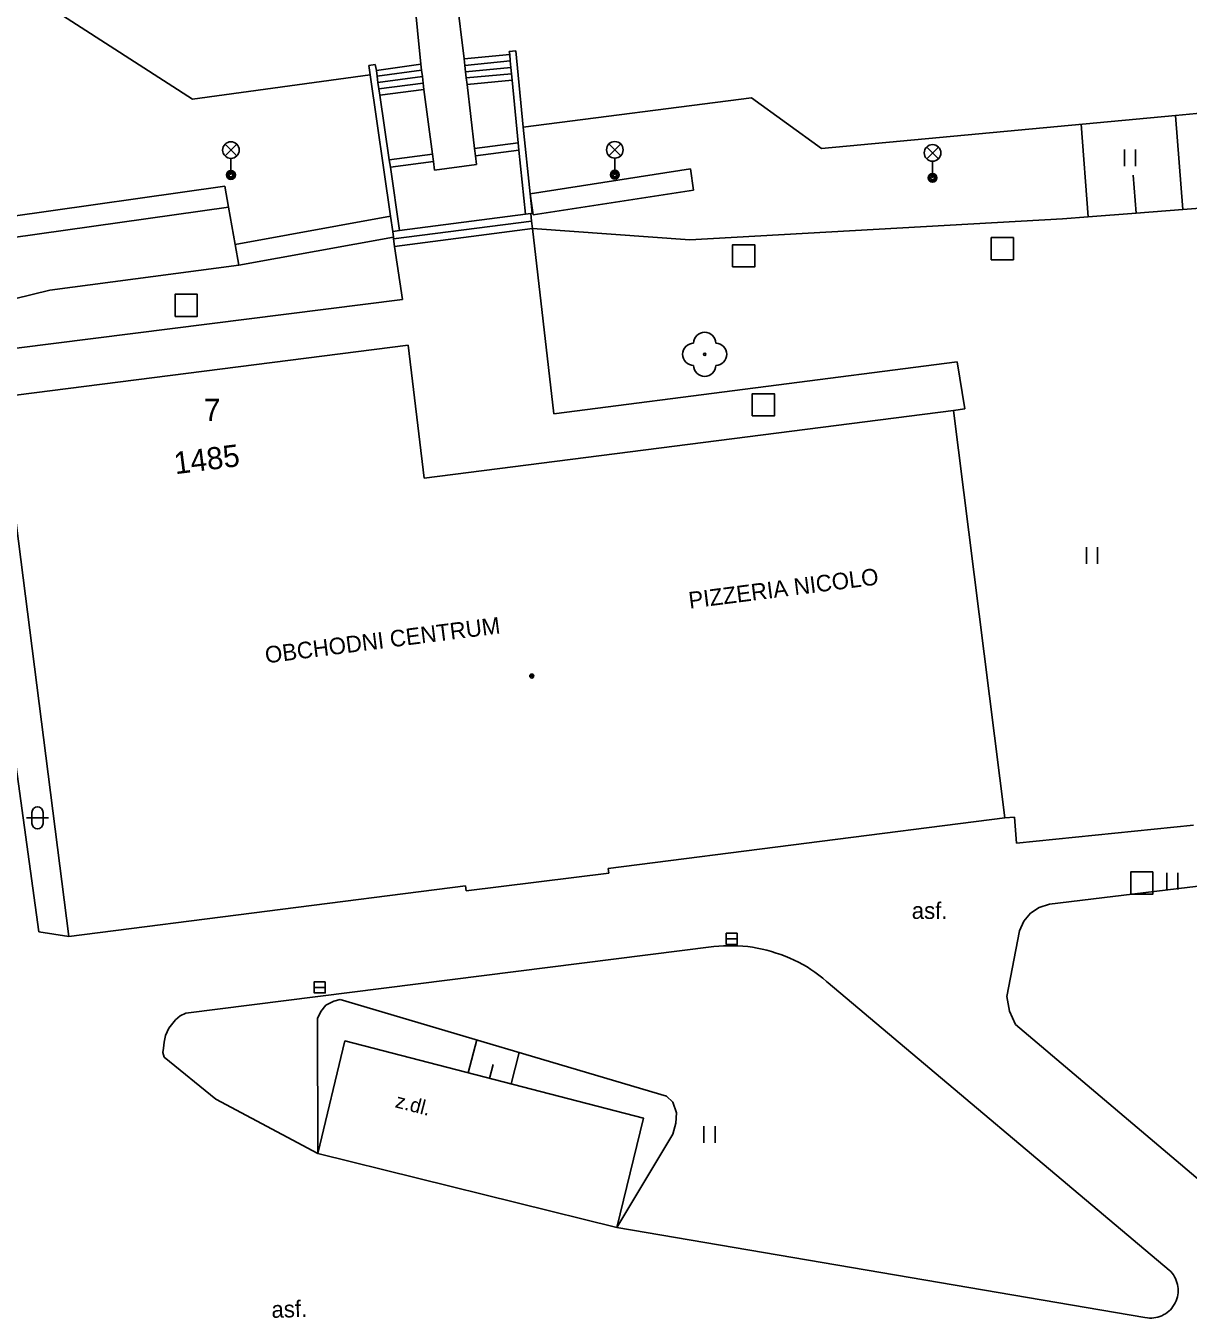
# Model space of a CAD drawing. Extents: x -641829 to -641525, y -1114855 to -1114359.
# Drawn here: x -641715.8 to -641663.3, y -1114729.3 to -1114670.9 of the extents above; entities that cross this region are included whole.
import ezdxf

# ---------------------------------------------------------------- set-up
doc = ezdxf.new("R2010")
doc.units = 0
for name, color, linetype in [('Vrstva 10', 7, 'Continuous'), ('Vrstva 11', 7, 'Continuous'), ('Vrstva 14', 7, 'Continuous'), ('Vrstva 15', 7, 'Continuous'), ('Vrstva 22', 7, 'Continuous'), ('Vrstva 26', 7, 'Continuous'), ('Vrstva 27', 7, 'Continuous'), ('Vrstva 33', 7, 'Continuous'), ('Vrstva 36', 7, 'Continuous'), ('Vrstva 39', 7, 'Continuous'), ('Vrstva 40', 7, 'Continuous'), ('Vrstva 41', 7, 'Continuous'), ('Vrstva 46', 7, 'Continuous'), ('Vrstva 47', 7, 'Continuous'), ('Vrstva 5', 7, 'Continuous')]:
    doc.layers.add(name, color=color, linetype=linetype)

msp = doc.modelspace()

# ---------------------------------------------------------------- linework, layer by layer
at = {"layer": 'Vrstva 10'}
for p, q in [((-641718.65, -1114686.73), (-641715.19, -1114711.87)), ((-641671.12, -1114706.68), (-641671.56, -1114706.72)), ((-641671.03, -1114707.86), (-641671.12, -1114706.68)), ((-641715.19, -1114711.87), (-641713.83, -1114712.08)), ((-641684.7, -1114712.53), (-641708.55, -1114715.54)), ((-641684.7, -1114712.53), (-641684.48, -1114712.51)), ((-641684.48, -1114712.51), (-641684.26, -1114712.5)), ((-641684.26, -1114712.5), (-641684.04, -1114712.49)), ((-641684.04, -1114712.49), (-641683.82, -1114712.49)), ((-641683.82, -1114712.49), (-641683.61, -1114712.5)), ((-641683.61, -1114712.5), (-641683.39, -1114712.51)), ((-641683.39, -1114712.51), (-641683.17, -1114712.53)), ((-641683.17, -1114712.53), (-641682.95, -1114712.56)), ((-641682.95, -1114712.56), (-641682.74, -1114712.6)), ((-641682.74, -1114712.6), (-641682.52, -1114712.64)), ((-641682.52, -1114712.64), (-641682.31, -1114712.69)), ((-641682.31, -1114712.69), (-641682.1, -1114712.75)), ((-641682.1, -1114712.75), (-641681.89, -1114712.82)), ((-641681.89, -1114712.82), (-641681.68, -1114712.89)), ((-641681.68, -1114712.89), (-641681.47, -1114712.96)), ((-641681.47, -1114712.96), (-641681.27, -1114713.05)), ((-641681.27, -1114713.05), (-641681.07, -1114713.14)), ((-641681.07, -1114713.14), (-641680.88, -1114713.24)), ((-641680.88, -1114713.24), (-641680.68, -1114713.34)), ((-641680.68, -1114713.34), (-641680.49, -1114713.45)), ((-641680.49, -1114713.45), (-641680.31, -1114713.57)), ((-641680.31, -1114713.57), (-641680.13, -1114713.69)), ((-641680.13, -1114713.69), (-641679.95, -1114713.82)), ((-641679.95, -1114713.82), (-641679.77, -1114713.96)), ((-641679.77, -1114713.96), (-641679.61, -1114714.1)), ((-641679.61, -1114714.1), (-641679.53, -1114714.16)), ((-641664.13, -1114727.14), (-641679.53, -1114714.16)), ((-641709.01, -1114715.83), (-641709.31, -1114716.22)), ((-641708.8, -1114715.65), (-641709.01, -1114715.83)), ((-641708.55, -1114715.54), (-641708.8, -1114715.65)), ((-641660.27, -1114725.2), (-641671.07, -1114716.05)), ((-641709.46, -1114716.55), (-641709.52, -1114716.84)), ((-641709.31, -1114716.22), (-641709.46, -1114716.55)), ((-641709.58, -1114717.31), (-641709.56, -1114717.11)), ((-641709.56, -1114717.11), (-641709.52, -1114716.84)), ((-641709.52, -1114717.52), (-641709.58, -1114717.31)), ((-641707.19, -1114719.42), (-641709.52, -1114717.52)), ((-641702.59, -1114721.88), (-641707.19, -1114719.42)), ((-641702.59, -1114721.88), (-641689.08, -1114725.22)), ((-641689.08, -1114725.22), (-641665.23, -1114729.28)), ((-641664.13, -1114727.14), (-641664.06, -1114727.21)), ((-641664.06, -1114727.21), (-641664, -1114727.28)), ((-641664, -1114727.28), (-641663.94, -1114727.36)), ((-641663.94, -1114727.36), (-641663.89, -1114727.44)), ((-641663.89, -1114727.44), (-641663.85, -1114727.52)), ((-641663.85, -1114727.52), (-641663.81, -1114727.61)), ((-641663.81, -1114727.61), (-641663.78, -1114727.7)), ((-641663.78, -1114727.7), (-641663.76, -1114727.79)), ((-641663.76, -1114728.35), (-641663.79, -1114728.44)), ((-641663.76, -1114727.79), (-641663.74, -1114727.88)), ((-641663.74, -1114728.26), (-641663.76, -1114728.35)), ((-641663.74, -1114727.88), (-641663.73, -1114727.97)), ((-641663.73, -1114728.16), (-641663.74, -1114728.26)), ((-641663.73, -1114727.97), (-641663.73, -1114728.07)), ((-641663.73, -1114728.07), (-641663.73, -1114728.16)), ((-641664.08, -1114728.93), (-641664.15, -1114728.99)), ((-641664.01, -1114728.86), (-641664.08, -1114728.93)), ((-641663.96, -1114728.78), (-641664.01, -1114728.86)), ((-641663.9, -1114728.7), (-641663.96, -1114728.78)), ((-641663.86, -1114728.62), (-641663.9, -1114728.7)), ((-641663.82, -1114728.53), (-641663.86, -1114728.62)), ((-641663.79, -1114728.44), (-641663.82, -1114728.53)), ((-641665.11, -1114729.3), (-641665.23, -1114729.28)), ((-641665.02, -1114729.31), (-641665.11, -1114729.3)), ((-641664.92, -1114729.31), (-641665.02, -1114729.31)), ((-641664.83, -1114729.3), (-641664.92, -1114729.31)), ((-641664.73, -1114729.28), (-641664.83, -1114729.3)), ((-641664.64, -1114729.26), (-641664.73, -1114729.28)), ((-641664.55, -1114729.23), (-641664.64, -1114729.26)), ((-641664.46, -1114729.2), (-641664.55, -1114729.23)), ((-641664.38, -1114729.15), (-641664.46, -1114729.2)), ((-641664.3, -1114729.11), (-641664.38, -1114729.15)), ((-641664.22, -1114729.05), (-641664.3, -1114729.11)), ((-641664.15, -1114728.99), (-641664.22, -1114729.05))]:
    msp.add_line(p, q, dxfattribs=at)
at = {"layer": 'Vrstva 11'}
for p, q in [((-641698.27, -1114669.33), (-641697.94, -1114672.68)), ((-641695.98, -1114672.44), (-641696.38, -1114669.14)), ((-641708.25, -1114674.26), (-641714.58, -1114670.18)), ((-641693.92, -1114672.24), (-641695.98, -1114672.44)), ((-641693.94, -1114672.1), (-641693.64, -1114672.07)), ((-641693.92, -1114672.24), (-641693.94, -1114672.1)), ((-641693.92, -1114672.24), (-641693.9, -1114672.53)), ((-641693.31, -1114675.52), (-641693.64, -1114672.07)), ((-641699.99, -1114672.69), (-641700.28, -1114672.73)), ((-641700.22, -1114673.16), (-641700.28, -1114672.73)), ((-641699.94, -1114672.97), (-641699.99, -1114672.69)), ((-641699.94, -1114672.97), (-641697.94, -1114672.68)), ((-641697.94, -1114672.68), (-641697.9, -1114672.95)), ((-641695.98, -1114672.44), (-641695.94, -1114672.73)), ((-641693.9, -1114672.53), (-641695.94, -1114672.73)), ((-641695.94, -1114672.73), (-641695.91, -1114673.02)), ((-641693.87, -1114672.82), (-641695.91, -1114673.02)), ((-641693.9, -1114672.53), (-641693.87, -1114672.82)), ((-641693.87, -1114672.82), (-641693.84, -1114673.11)), ((-641700.22, -1114673.16), (-641708.25, -1114674.26)), ((-641699.3, -1114679.54), (-641700.22, -1114673.16)), ((-641699.94, -1114672.97), (-641699.91, -1114673.22)), ((-641697.9, -1114672.95), (-641699.91, -1114673.22)), ((-641699.91, -1114673.22), (-641699.87, -1114673.5)), ((-641697.86, -1114673.24), (-641699.87, -1114673.5)), ((-641699.87, -1114673.5), (-641699.83, -1114673.79)), ((-641697.9, -1114672.95), (-641697.86, -1114673.24)), ((-641697.86, -1114673.24), (-641697.82, -1114673.53)), ((-641695.91, -1114673.02), (-641695.88, -1114673.3)), ((-641693.84, -1114673.11), (-641695.88, -1114673.3)), ((-641695.88, -1114673.3), (-641695.84, -1114673.59)), ((-641693.81, -1114673.4), (-641695.84, -1114673.59)), ((-641693.84, -1114673.11), (-641693.81, -1114673.4)), ((-641693.6, -1114675.59), (-641693.81, -1114673.4)), ((-641697.82, -1114673.53), (-641699.83, -1114673.79)), ((-641699.83, -1114673.79), (-641699.78, -1114674.08)), ((-641697.79, -1114673.82), (-641699.78, -1114674.08)), ((-641699.36, -1114677), (-641699.78, -1114674.08)), ((-641697.82, -1114673.53), (-641697.79, -1114673.82)), ((-641697.4, -1114676.74), (-641697.79, -1114673.82)), ((-641695.51, -1114676.49), (-641695.84, -1114673.59)), ((-641663.84, -1114674.99), (-641653.39, -1114674.02)), ((-641682.99, -1114674.19), (-641693.31, -1114675.52)), ((-641679.83, -1114676.48), (-641682.99, -1114674.19)), ((-641679.83, -1114676.48), (-641663.84, -1114674.99)), ((-641693.54, -1114676.23), (-641693.6, -1114675.59)), ((-641693, -1114678.53), (-641693.31, -1114675.52)), ((-641693.54, -1114676.23), (-641695.51, -1114676.49)), ((-641693.5, -1114676.56), (-641693.54, -1114676.23)), ((-641699.36, -1114677), (-641697.4, -1114676.74)), ((-641699.31, -1114677.33), (-641699.36, -1114677)), ((-641697.36, -1114677.07), (-641697.4, -1114676.74)), ((-641695.47, -1114676.82), (-641695.51, -1114676.49)), ((-641693.5, -1114676.56), (-641695.47, -1114676.82)), ((-641695.42, -1114677.21), (-641695.47, -1114676.82)), ((-641693.21, -1114679.45), (-641693.5, -1114676.56)), ((-641699.31, -1114677.33), (-641697.36, -1114677.07)), ((-641698.9, -1114680.19), (-641699.31, -1114677.33)), ((-641697.31, -1114677.46), (-641697.36, -1114677.07)), ((-641697.31, -1114677.46), (-641695.42, -1114677.21)), ((-641685.76, -1114677.41), (-641693, -1114678.53)), ((-641685.61, -1114678.36), (-641685.76, -1114677.41)), ((-641716.55, -1114679.57), (-641706.79, -1114678.18)), ((-641706.79, -1114678.18), (-641706.62, -1114679.13)), ((-641692.86, -1114679.48), (-641693, -1114678.53)), ((-641692.91, -1114679.41), (-641693, -1114678.53)), ((-641685.61, -1114678.36), (-641692.86, -1114679.48)), ((-641716.43, -1114680.52), (-641706.62, -1114679.13)), ((-641706.62, -1114679.13), (-641706.32, -1114680.82)), ((-641706.32, -1114680.82), (-641699.3, -1114679.54)), ((-641699.19, -1114680.23), (-641699.3, -1114679.54)), ((-641692.93, -1114679.76), (-641699.16, -1114680.57)), ((-641693.21, -1114679.45), (-641698.9, -1114680.19)), ((-641693.21, -1114679.45), (-641692.97, -1114679.42)), ((-641692.97, -1114679.42), (-641692.91, -1114679.41)), ((-641692.97, -1114679.42), (-641692.93, -1114679.76)), ((-641692.93, -1114679.76), (-641692.89, -1114680.1)), ((-641706.15, -1114681.76), (-641699.16, -1114680.49)), ((-641699.19, -1114680.23), (-641698.9, -1114680.19)), ((-641699.16, -1114680.49), (-641699.19, -1114680.23)), ((-641699.16, -1114680.57), (-641699.16, -1114680.49)), ((-641692.89, -1114680.1), (-641699.12, -1114680.91)), ((-641692.89, -1114680.1), (-641691.92, -1114688.47)), ((-641706.32, -1114680.82), (-641706.15, -1114681.76)), ((-641699.12, -1114680.91), (-641699.16, -1114680.57)), ((-641698.76, -1114683.3), (-641699.12, -1114680.91)), ((-641706.15, -1114681.76), (-641714.69, -1114682.88)), ((-641714.69, -1114682.88), (-641718.69, -1114683.87)), ((-641716.19, -1114685.51), (-641698.76, -1114683.3)), ((-641691.92, -1114688.47), (-641673.71, -1114686.12)), ((-641673.71, -1114686.12), (-641673.36, -1114688.25)), ((-641673.87, -1114688.32), (-641673.36, -1114688.25)), ((-641671.03, -1114707.86), (-641663.04, -1114707.04)), ((-641671.47, -1114714.78), (-641670.89, -1114711.82))]:
    msp.add_line(p, q, dxfattribs=at)
for points in [[(-641669.54, -1114710.61), (-641660.46, -1114709.52), (-641658.93, -1114710.35)], [(-641669.54, -1114710.61), (-641670.01, -1114710.77), (-641670.39, -1114711.02), (-641670.69, -1114711.38), (-641670.89, -1114711.82)], [(-641671.47, -1114714.78), (-641671.34, -1114715.44), (-641671.07, -1114716.05)], [(-641702.59, -1114721.88), (-641701.36, -1114716.79), (-641687.87, -1114720.28), (-641689.08, -1114725.22)]]:
    msp.add_lwpolyline(points, dxfattribs=at)
at = {"layer": 'Vrstva 14'}
for p, q in [((-641663.51, -1114679.24), (-641665.63, -1114679.41)), ((-641660.32, -1114679), (-641663.51, -1114679.24)), ((-641668.95, -1114679.66), (-641685.78, -1114680.61)), ((-641667.79, -1114679.57), (-641668.95, -1114679.66)), ((-641665.63, -1114679.41), (-641667.79, -1114679.57)), ((-641685.78, -1114680.61), (-641692.89, -1114680.1)), ((-641701.57, -1114714.92), (-641686.84, -1114719.28)), ((-641702.59, -1114721.88), (-641702.6, -1114715.78)), ((-641686.55, -1114721), (-641689.08, -1114725.22))]:
    msp.add_line(p, q, dxfattribs=at)
for points in [[(-641701.57, -1114714.92), (-641701.86, -1114714.99), (-641702.22, -1114715.17), (-641702.45, -1114715.46), (-641702.6, -1114715.78)], [(-641686.55, -1114721), (-641686.41, -1114720.51), (-641686.39, -1114720.03), (-641686.55, -1114719.56), (-641686.84, -1114719.28)]]:
    msp.add_lwpolyline(points, dxfattribs=at)
at = {"layer": 'Vrstva 15'}
for p, q in [((-641663.51, -1114679.24), (-641663.84, -1114674.99)), ((-641667.79, -1114679.57), (-641668.11, -1114675.39)), ((-641665.63, -1114679.41), (-641665.76, -1114677.69)), ((-641695.79, -1114718.23), (-641695.41, -1114716.74)), ((-641694.83, -1114718.48), (-641694.66, -1114717.85)), ((-641693.86, -1114718.73), (-641693.49, -1114717.31))]:
    msp.add_line(p, q, dxfattribs=at)
at = {"layer": 'Vrstva 22'}
msp.add_circle((-641685.11, -1114685.78), 0.05, dxfattribs=at)
for centre, start, end in [((-641685.11, -1114685.28), 0, 180), ((-641685.61, -1114685.78), 90, 270), ((-641684.61, -1114685.78), 270, 90), ((-641685.11, -1114686.28), 180, 0)]:
    msp.add_arc(centre, 0.5, start, end, dxfattribs=at)
at = {"layer": 'Vrstva 26'}
for points in [[(-641683.85, -1114681.83), (-641682.85, -1114681.83), (-641682.85, -1114680.83), (-641683.85, -1114680.83)], [(-641672.17, -1114681.51), (-641671.17, -1114681.51), (-641671.17, -1114680.51), (-641672.17, -1114680.51)], [(-641709.03, -1114684.07), (-641708.03, -1114684.07), (-641708.03, -1114683.07), (-641709.03, -1114683.07)], [(-641682.96, -1114688.56), (-641681.96, -1114688.56), (-641681.96, -1114687.56), (-641682.96, -1114687.56)], [(-641664.87, -1114709.16), (-641665.87, -1114709.16), (-641665.87, -1114710.16), (-641664.87, -1114710.16)]]:
    msp.add_lwpolyline(points, close=True, dxfattribs=at)
at = {"layer": 'Vrstva 27'}
for p, q in [((-641683.64, -1114712.18), (-641684.14, -1114712.18)), ((-641702.25, -1114714.37), (-641702.75, -1114714.37))]:
    msp.add_line(p, q, dxfattribs=at)
for points in [[(-641683.64, -1114711.93), (-641684.14, -1114711.93), (-641684.14, -1114712.43), (-641683.64, -1114712.43)], [(-641702.25, -1114714.12), (-641702.75, -1114714.12), (-641702.75, -1114714.62), (-641702.25, -1114714.62)]]:
    msp.add_lwpolyline(points, close=True, dxfattribs=at)
at = {"layer": 'Vrstva 33'}
for p, q in [((-641706.774, -1114676.82), (-641706.246, -1114676.29)), ((-641706.774, -1114676.29), (-641706.246, -1114676.82)), ((-641689.436, -1114676.81), (-641688.904, -1114676.28)), ((-641689.436, -1114676.28), (-641688.904, -1114676.81)), ((-641675.084, -1114676.95), (-641674.556, -1114676.42)), ((-641675.084, -1114676.42), (-641674.556, -1114676.95)), ((-641706.51, -1114676.93), (-641706.51, -1114677.68)), ((-641689.17, -1114676.92), (-641689.17, -1114677.67)), ((-641674.82, -1114677.06), (-641674.82, -1114677.81))]:
    msp.add_line(p, q, dxfattribs=at)
for centre, radius in [((-641706.51, -1114676.555), 0.375), ((-641689.17, -1114676.545), 0.375), ((-641674.82, -1114676.685), 0.375), ((-641706.51, -1114677.68), 0.2), ((-641706.51, -1114677.68), 0.145), ((-641689.17, -1114677.67), 0.2), ((-641689.17, -1114677.67), 0.145), ((-641689.17, -1114677.67), 0.0876), ((-641706.51, -1114677.68), 0.0876), ((-641674.82, -1114677.81), 0.2), ((-641674.82, -1114677.81), 0.145), ((-641674.82, -1114677.81), 0.0876)]:
    msp.add_circle(centre, radius, dxfattribs=at)
at = {"layer": 'Vrstva 36'}
for p, q in [((-641666.154, -1114677.283), (-641666.154, -1114676.533)), ((-641665.654, -1114677.283), (-641665.654, -1114676.533)), ((-641667.874, -1114695.244), (-641667.874, -1114694.492)), ((-641667.374, -1114695.244), (-641667.374, -1114694.492)), ((-641715.746, -1114706.716), (-641714.746, -1114706.716)), ((-641715.496, -1114706.466), (-641715.496, -1114706.966)), ((-641714.996, -1114706.466), (-641714.996, -1114706.966)), ((-641664.234, -1114709.953), (-641664.234, -1114709.203)), ((-641663.734, -1114709.953), (-641663.734, -1114709.203)), ((-641685.144, -1114721.394), (-641685.144, -1114720.642)), ((-641684.644, -1114721.394), (-641684.644, -1114720.642))]:
    msp.add_line(p, q, dxfattribs=at)
for centre, start, end in [((-641715.246, -1114706.466), 0, 180), ((-641715.246, -1114706.966), 180, 0)]:
    msp.add_arc(centre, 0.25, start, end, dxfattribs=at)
at = {"layer": 'Vrstva 39'}
for radius in [0.09, 0.0398]:
    msp.add_circle((-641692.92, -1114700.31), radius, dxfattribs=at)
at = {"layer": 'Vrstva 5'}
for p, q in [((-641698.5, -1114685.37), (-641716.93, -1114687.71)), ((-641697.78, -1114691.38), (-641698.5, -1114685.37)), ((-641713.83, -1114712.08), (-641716.93, -1114687.71)), ((-641673.87, -1114688.32), (-641697.78, -1114691.38)), ((-641673.87, -1114688.32), (-641671.56, -1114706.72)), ((-641689.47, -1114709), (-641671.56, -1114706.72)), ((-641689.47, -1114709), (-641689.44, -1114709.22)), ((-641689.44, -1114709.22), (-641695.88, -1114710.01)), ((-641695.91, -1114709.79), (-641713.83, -1114712.08)), ((-641695.91, -1114709.79), (-641695.88, -1114710.01))]:
    msp.add_line(p, q, dxfattribs=at)

# ---------------------------------------------------------------- texts
at = {"layer": 'Vrstva 40'}
msp.add_text('z.dl.', height=0.65, rotation=345.49503, dxfattribs=at).set_placement((-641699.13, -1114719.78))
at = {"layer": 'Vrstva 41'}
for s, rotation, p in [('PIZZERIA NICOLO', 7.30213, (-641685.79, -1114697.27)), ('OBCHODNI CENTRUM', 7.30213, (-641704.92, -1114699.74)), ('asf.', 1.75663, (-641704.67, -1114729.3))]:
    msp.add_text(s, height=0.7499, rotation=rotation, dxfattribs=at).set_placement(p)
msp.add_text('asf.', height=0.75, dxfattribs=at).set_placement((-641675.76, -1114711.28))
at = {"layer": 'Vrstva 46'}
msp.add_text('7', height=1, dxfattribs=at).set_placement((-641707.73, -1114688.79))
at = {"layer": 'Vrstva 47'}
msp.add_text('1485', height=1, rotation=7.23673, dxfattribs=at).set_placement((-641709.02, -1114691.2))

doc.saveas('drawing.dxf')
